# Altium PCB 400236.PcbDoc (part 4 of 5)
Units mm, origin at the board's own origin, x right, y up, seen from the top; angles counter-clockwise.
Board outline 136.53 x 63.5 mm, 4 copper layers (Top Layer, Mid-Layer 1, Mid-Layer 2, Bottom Layer), stack 1.49 mm thick; 344 components, 236 nets, 1364 pads, 1393 vias.
Unrouted connection lines stored in the file: 6.
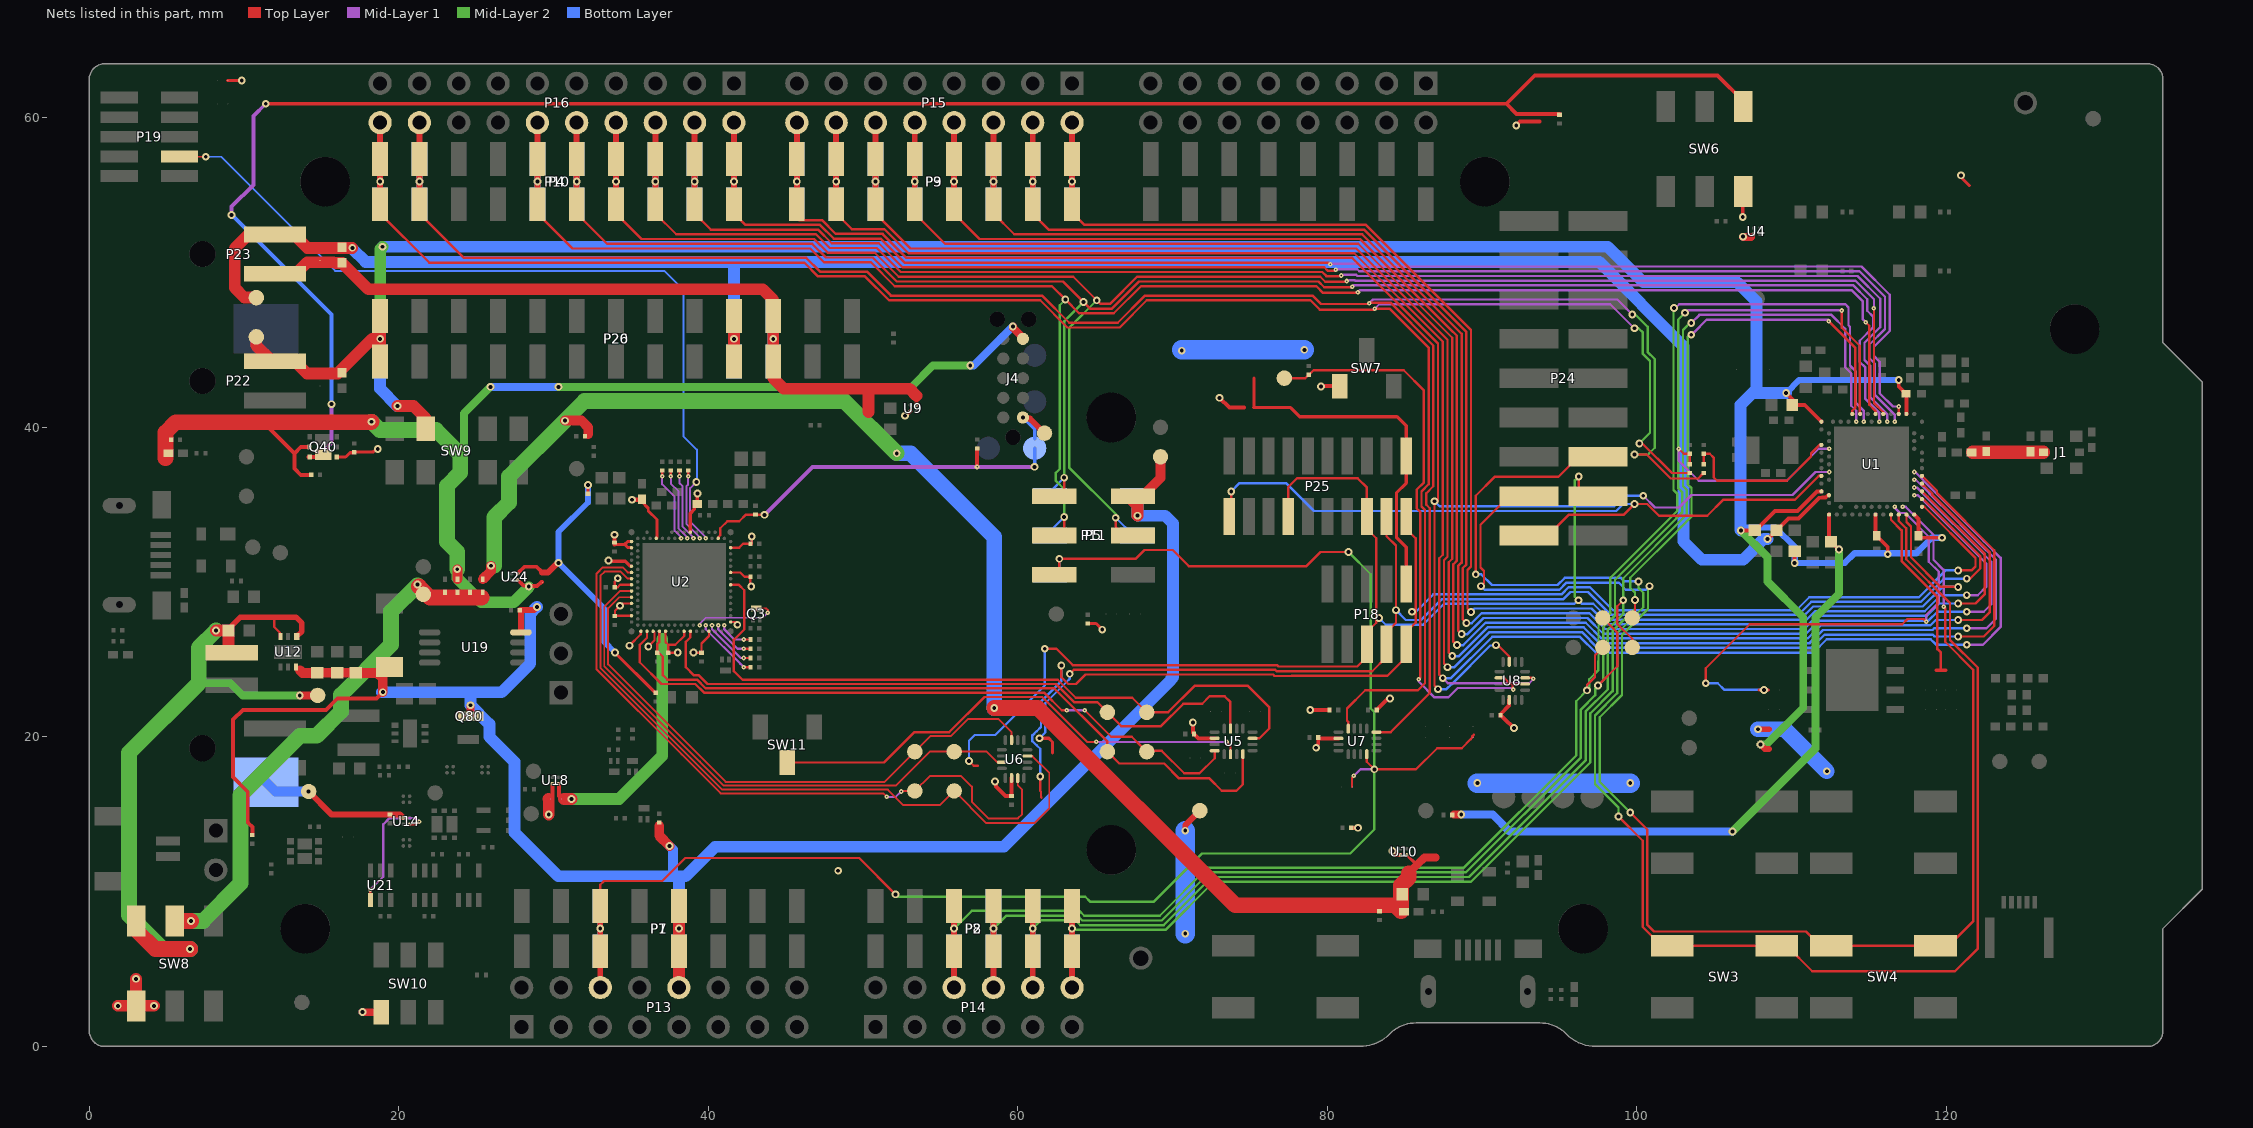
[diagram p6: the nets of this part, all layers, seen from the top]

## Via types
v1: diameter 0.5, hole 0.25, Top Layer to Bottom Layer, tented both sides, 1166 vias
v2: diameter 0.3, hole 0.1, Top Layer to Mid-Layer 1, tented top, 227 vias

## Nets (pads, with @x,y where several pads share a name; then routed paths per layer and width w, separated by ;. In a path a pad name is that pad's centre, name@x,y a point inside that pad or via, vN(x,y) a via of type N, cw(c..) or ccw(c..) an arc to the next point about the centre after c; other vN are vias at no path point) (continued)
P0.22: SB15.1 SB25.1 U1.AD18 | length 12
  Top Layer w0.152: U1.AD18@116.414,34.367 116.414,34.03 117.096,33.347 117.096,31.359 119.411,29.045 119.411,25.674 119.634,25.451 119.634,24.308
  Top Layer w0.203: SB15.1@119.337,24.308 119.634,24.308 119.957,24.308
P0.23: SB10.1 SB20.1 U1.AC19 | length 30.3
  Top Layer w0.152: v1(104.445,23.47) 104.445,24.434 107.29,27.28 117.14,27.28 117.478,27.617 118.509,27.617 v2(118.694,27.432)
  Top Layer w0.203: 107.881,23.038 v1(108.204,23.038) SB10.1@108.501,23.038
  Mid-Layer 1 w0.152: v2(116.664,34.867) 116.664,34.8 116.998,34.465 117.329,34.465 118.855,32.939 118.855,31.325 119.509,30.671 119.509,28.688 118.694,27.872 v2(118.694,27.432)
  Bottom Layer w0.152: v1(104.445,23.47) 105.225,23.47 105.656,23.038 v1(108.204,23.038)
P0.24: P24.14 SW3.2 U1.AD20 | length 103.7
  Top Layer w0.152: v1(89.586,30.505) 89.586,35.585 90.805,36.805 94.92,36.805 96.215,38.1 P24.14@97.472,38.1 ; v1(98.806,14.859) 100.37,13.295 100.37,7.72 101.588,6.502 SW3.2@102.278,6.502 SW3.2@109.028,6.502 109.691,6.502 111.328,4.864 120.548,4.864 122.025,6.341 122.025,24.468 120.221,26.272 120.221,28.663 117.401,31.482 117.401,33.473 116.914,33.961 U1.AD20@116.914,34.367
  Mid-Layer 2 w0.152: v1(98.806,14.859) 98.806,15.447 97.29,16.963 97.29,21.394 98.73,22.834 98.73,26.71 98.977,26.957 98.98,26.957 100.404,28.38 100.404,29.319 100.101,29.621 v1(100.101,30.048)
  Bottom Layer w0.152: v1(89.586,30.505) 89.941,30.505 90.627,29.82 94.871,29.82 95.328,30.277 98.948,30.277 99.177,30.048 v1(100.101,30.048)
P0.25: P24.15 SW4.2 U1.AC21 | length 95.1
  Top Layer w0.152: v1(89.916,29.743) 90.119,29.947 90.119,30.726 89.891,30.955 89.891,33.706 91.745,35.56 P24.15@93.027,35.56 ; v1(99.568,15.113) 100.675,14.006 100.675,7.846 101.09,7.43 110.921,7.43 111.85,6.502 SW4.2@112.54,6.502 SW4.2@119.29,6.502 120.137,6.502 121.72,8.085 121.72,24.345 119.918,26.147 119.918,28.316 v2(119.812,28.423) ; v2@119.812,28.448 v2@119.825,28.435
  Mid-Layer 1 w0.152: v2(117.164,34.867) 117.355,34.867 119.158,33.065 119.158,31.45 119.812,30.796 v2(119.812,28.423)
  Mid-Layer 2 w0.152: v1(99.568,15.113) 97.595,17.086 97.595,21.268 99.035,22.708 99.035,26.584 100.711,28.26 100.711,29.642 v1(100.813,29.743)
  Bottom Layer w0.152: v1(89.916,29.743) 90.145,29.515 94.997,29.515 95.455,29.972 98.822,29.972 99.279,29.515 100.584,29.515 v1(100.813,29.743)
P0.26: C51.2 R1.2 U1.G1 | length 10.8
  Top Layer w0.15: 109.55,36.551 109.674,36.551 109.675,36.552 111.244,38.12 111.244,38.214
  Top Layer w0.152: R1.2@104.318,37.66 C51.2@104.318,38.298 104.704,38.298 104.953,38.049 104.953,36.779 105.181,36.551 109.55,36.551 ; 111.244,38.214 111.244,38.32 111.791,38.867 U1.G1@111.914,38.867
P0.27: C52.2 R2.2 U1.H2 | length 13.3
  Top Layer w0.152: v2(102.692,38.608) 102.7,38.616 103.019,38.298 C52.2@103.403,38.298 R2.2@103.403,37.66
  Mid-Layer 1 w0.152: v2(102.692,38.608) 102.692,37.846 103.988,36.551 109.674,36.551 111.741,38.617 v2@112.378,38.617
  other v2: 112.414,38.617
P0.28/AIN4: P2.3 P8.3 P14.6 TP44.1 U1.B11 | length 107.4
  Top Layer w0.152: v1(96.774,23.012) 96.774,23.354 97.285,23.865 97.285,25.276 TP44.1@97.79,25.781
  Top Layer w0.381: P14.6@55.88,3.81 P2.3@55.88,6.155 v1(55.88,7.62) P2.3@55.88,9.085
  Mid-Layer 1 w0.152: v1@102.438,47.658 102.733,47.953 113.466,47.953 113.665,47.754 113.665,46.598 113.767,46.496 113.767,43.993 114.151,43.608 114.151,41.579 114.664,41.067 v2(114.664,40.367)
  Mid-Layer 2 w0.152: v1(55.88,7.62) 57.023,8.763 63.973,8.763 64.289,8.448 69.164,8.448 72.273,11.557 88.824,11.557 96.071,18.804 96.071,22.31 v1(96.774,23.012) 96.915,23.153 96.915,23.728 97.506,24.319 97.506,24.887 97.511,24.892 97.511,27.215 98.273,27.977 98.273,30.279 102.614,34.62 102.614,35.704 102.36,35.958 102.36,42.339 102.362,42.342 102.362,47.683 v1(102.387,47.709)
  Bottom Layer w0.381: P8.3@55.88,6.155 v1(55.88,7.62) P8.3@55.88,9.085
P0.29/AIN5: P2.4 P8.4 P14.8 TP45.1 U1.A10 | length 106
  Top Layer w0.152: v1(97.485,23.317) 98.73,24.562 98.73,26.746 TP45.1@97.79,27.686 ; v2(113.233,47.549) 113.233,46.445 114.397,45.281 114.397,40.884 U1.A10@114.414,40.867 ; v2@113.309,47.549 v2@113.309,47.574
  Top Layer w0.381: P14.8@58.42,3.81 P2.4@58.42,6.155 v1(58.42,7.62) P2.4@58.42,9.085
  Mid-Layer 1 w0.152: v1(103.099,47.404) 103.269,47.574 v2@113.233,47.574
  Mid-Layer 2 w0.152: v1(58.42,7.62) 59.258,8.458 63.847,8.458 64.162,8.143 69.29,8.143 72.399,11.252 88.95,11.252 96.376,18.678 96.376,21.773 97.305,22.702 97.305,23.137 v1(97.485,23.317) 97.815,23.647 97.815,27.089 98.577,27.851 98.577,30.153 102.54,34.115 102.54,34.119 102.916,34.495 102.916,35.829 102.667,36.078 102.667,46.972 v1(103.099,47.404)
  Bottom Layer w0.381: P8.4@58.42,6.155 v1(58.42,7.62) P8.4@58.42,9.652
P0.30/AIN6: P2.5 P8.5 P14.10 TP46.1 U1.B9 | length 101.3
  Top Layer w0.152: v1(99.111,28.829) 98.73,28.448 98.73,27.305 99.695,26.34 TP46.1@99.695,25.781
  Top Layer w0.381: P14.10@60.96,3.81 P2.5@60.96,6.155 v1(60.96,7.62) P2.5@60.96,9.085
  Mid-Layer 1 w0.152: v1(103.505,46.744) 104.033,47.272 112.56,47.272 113.462,46.37 113.462,43.867 113.846,43.482 113.846,41.399 114.164,41.081 v2(114.164,40.367)
  Mid-Layer 2 w0.152: v1(60.96,7.62) 61.493,8.153 63.721,8.153 64.036,7.838 69.417,7.838 72.526,10.947 89.154,10.947 96.681,18.474 96.681,21.647 98.12,23.086 98.12,26.962 99.111,27.953 v1(99.111,28.829) 99.111,30.255 103.218,34.363 103.218,35.954 102.972,36.201 102.972,46.301 103.541,46.871 v1@103.657,46.871
  Bottom Layer w0.381: P8.5@60.96,6.155 v1(60.96,7.62) P8.5@60.96,9.652
P0.31/AIN7: P2.6 P8.6 P14.12 TP47.1 U1.A8 | length 94.5
  Top Layer w0.152: TP47.1@99.695,27.686 99.873,27.864 v1(99.873,28.854) ; v2@112.446,46.863 112.446,46.801 114.092,45.155 114.092,41.256 113.914,41.077 U1.A8@113.914,40.867
  Top Layer w0.381: P14.12@63.5,3.81 P2.6@63.5,6.155 v1(63.5,7.62) P2.6@63.5,9.085
  Mid-Layer 1 w0.152: v1@103.53,46.109 103.657,46.109 104.513,46.965 112.344,46.965 v2@112.446,46.863
  Mid-Layer 2 w0.152: v1(63.5,7.62) 63.587,7.533 69.543,7.533 72.652,10.643 89.28,10.643 96.986,18.348 96.986,21.521 98.425,22.96 98.425,26.836 99.873,28.284 v1(99.873,28.854) 99.873,29.335 99.57,29.637 99.57,30.284 102.868,33.581 102.868,33.584 103.521,34.237 103.521,36.08 103.274,36.326 103.274,40.968 103.276,40.97 103.276,45.855 v1@103.53,46.109 ; v1@103.594,46.045 v1@103.657,46.109
  Bottom Layer w0.381: P8.6@63.5,6.155 v1(63.5,7.62) P8.6@63.5,9.085
  other v1: 103.505,45.982
  other v2: 112.395,46.863
P1.00: P18.6 P24.16 P25.6 P25.14 SB57.1 U1.AD22 | length 107.9
  Top Layer w0.152: v1(56.845,18.44) 57.15,18.136 57.222,18.136 SB57.1@57.396,18.136 ; v1(61.733,25.694) 62.498,25.694 63.552,24.64 76.75,24.64 76.837,24.554 81.932,24.554 82.55,25.171 P18.6@82.55,25.99 82.55,26.773 83.159,27.381 83.159,32.843 82.55,33.452 P25.6@82.55,34.245 82.55,36.119 81.952,36.716 78.042,36.716 77.47,36.144 P25.14@77.47,34.245 ; v1(96.241,36.83) 96.241,36.119 96.799,35.56 P24.16@97.472,35.56 ; U1.AD22@117.414,34.367 117.414,33.892 117.704,33.602 117.704,31.607 119.618,29.693 v1(120.752,29.693)
  Mid-Layer 2 w0.152: v1(96.215,28.829) 95.987,29.058 95.987,36.576 v1(96.241,36.83)
  Bottom Layer w0.152: v1(56.845,18.44) 56.845,19.753 57.217,20.125 58.541,20.125 61.738,23.322 61.738,25.689 v1(61.733,25.694) ; v1(83.337,27.686) 83.768,27.254 86.182,27.254 87.528,28.6 95.961,28.6 96.19,28.829 v1(96.215,28.829) 96.444,28.6 97.179,28.6 98.2,27.58 106.02,27.58 106.022,27.582 110.54,27.582 111.383,28.425 118.464,28.425 119.731,29.693 v1(120.752,29.693)
P1.01: P3.1 P9.1 P15.2 U1.Y23 | length 99.5
  Top Layer w0.152: P3.1@63.5,54.415 63.5,53.899 64.313,53.086 82.493,53.086 89.281,46.298 89.281,31.013 89.052,30.785 89.052,28.296 v1(89.281,28.067)
  Top Layer w0.381: P3.1@63.5,54.415 v1(63.5,55.88) P3.1@63.5,57.345 P15.2@63.5,59.69
  Mid-Layer 1 w0.152: v2(117.914,35.617) 118.154,35.617 122.58,31.191 122.58,29.718 122.022,29.159 v1(121.31,29.159)
  Bottom Layer w0.152: v1(89.281,28.067) 89.51,28.296 97.056,28.296 98.074,27.277 107.694,27.277 107.696,27.28 110.665,27.28 111.509,28.123 118.589,28.123 119.625,29.159 v1(121.31,29.159)
  Bottom Layer w0.381: P9.1@63.5,53.807 v1(63.5,55.88) P9.1@63.5,57.345
P1.02: P3.2 P9.2 P15.4 U1.W24 | length 102.5
  Top Layer w0.152: P3.2@60.96,54.415 60.96,53.797 61.976,52.781 82.367,52.781 88.976,46.172 88.976,31.14 88.748,30.911 88.748,27.584 v1(88.976,27.356) ; U1.W24@118.414,35.867 118.431,35.867 118.78,35.519 118.78,35.515 122.479,31.816 122.479,29.235 121.869,28.626 v1(120.752,28.626)
  Top Layer w0.381: P3.2@60.96,54.415 v1(60.96,55.88) P3.2@60.96,57.345 P15.4@60.96,59.69
  Bottom Layer w0.152: v1(88.976,27.356) 89.324,27.356 89.959,27.991 96.933,27.991 97.949,26.975 110.788,26.975 111.634,27.821 118.714,27.821 119.519,28.626 v1(120.752,28.626)
  Bottom Layer w0.381: P9.2@60.96,54.415 v1(60.96,55.88) P9.2@60.96,57.345
P1.03: P3.3 P9.3 P15.6 U1.V23 | length 107.4
  Top Layer w0.152: P3.3@58.42,54.415 58.42,53.823 59.766,52.476 82.241,52.476 88.671,46.046 88.671,31.266 88.443,31.037 88.443,26.873 v1(88.671,26.645)
  Top Layer w0.381: P3.3@58.42,54.415 v1(58.42,55.88) P3.3@58.42,57.345 P15.6@58.42,59.69
  Mid-Layer 1 w0.152: v2(117.914,36.117) 118.085,36.117 122.885,31.317 122.885,28.575 122.403,28.092 v1(121.31,28.092)
  Bottom Layer w0.152: v1(88.671,26.645) 89.052,26.645 90.094,27.686 96.81,27.686 97.826,26.67 110.911,26.67 111.759,27.518 118.839,27.518 119.414,28.092 v1(121.31,28.092)
  Bottom Layer w0.381: P9.3@58.42,54.415 v1(58.42,55.88) P9.3@58.42,57.345
P1.04: P3.4 P9.4 P15.8 U1.U24 | length 111
  Top Layer w0.152: P3.4@55.88,54.415 55.88,53.823 57.531,52.172 82.114,52.172 87.956,46.33 88.367,45.919 88.367,31.392 88.138,31.164 88.138,26.162 v1(88.367,25.933) ; U1.U24@118.414,36.367 118.414,36.307 118.487,36.233 118.565,36.233 119.084,35.714 119.084,35.641 122.783,31.942 122.783,28.041 122.301,27.559 v1(120.752,27.559)
  Top Layer w0.381: P3.4@55.88,54.415 v1(55.88,55.88) P3.4@55.88,57.345 P15.8@55.88,59.69
  Bottom Layer w0.152: v1(88.367,25.933) 88.773,25.933 90.221,27.381 96.687,27.381 97.703,26.365 111.034,26.365 111.885,27.216 118.965,27.216 119.308,27.559 v1(120.752,27.559)
  Bottom Layer w0.381: P9.4@55.88,54.415 v1(55.88,55.88) P9.4@55.88,57.345
P1.05: P3.5 P9.5 P15.10 U1.T23 | length 115.8
  Top Layer w0.152: P3.5@53.34,54.415 53.34,53.823 55.296,51.867 81.988,51.867 88.062,45.793 88.062,31.518 87.833,31.29 87.833,31.013 87.833,26.848 87.833,25.451 v1(88.062,25.222)
  Top Layer w0.381: P3.5@53.34,54.415 v1(53.34,55.88) P3.5@53.34,57.345 P15.10@53.34,59.69
  Mid-Layer 1 w0.152: v2(117.914,36.617) 118.016,36.617 119.684,34.95 119.686,34.95 122.072,32.564 122.072,32.561 123.19,31.444 123.19,27.635 122.58,27.026 v1(121.31,27.026)
  Bottom Layer w0.152: v1(88.062,25.222) 88.493,25.222 90.347,27.076 96.564,27.076 97.58,26.06 111.157,26.06 112.01,26.913 119.09,26.913 119.202,27.026 v1(121.31,27.026)
  Bottom Layer w0.381: P9.5@53.34,54.415 v1(53.34,55.88) P9.5@53.34,57.345
P1.06: P3.6 P9.6 P15.12 U1.R24 | length 119.5
  Top Layer w0.152: P3.6@50.8,54.415 50.8,53.823 53.061,51.562 81.862,51.562 87.757,45.667 87.757,31.645 87.528,31.416 87.528,31.14 87.528,31.115 87.528,26.822 87.528,24.74 v1(87.757,24.511) ; U1.R24@118.414,36.867 118.431,36.867 119.389,35.909 119.389,35.767 123.088,32.068 123.088,27.178 122.403,26.492 v1(120.752,26.492)
  Top Layer w0.381: P3.6@50.8,54.415 v1(50.8,55.88) P3.6@50.8,57.345 P15.12@50.8,59.69
  Bottom Layer w0.152: v1(87.757,24.511) 88.213,24.511 90.473,26.772 96.442,26.772 97.458,25.756 111.28,25.756 112.135,26.611 119.107,26.611 119.225,26.492 v1(120.752,26.492)
  Bottom Layer w0.381: P9.6@50.8,54.415 v1(50.8,55.88) P9.6@50.8,57.345
P1.07: P3.7 P9.7 P15.14 U1.P23 U8.3 | length 130.9
  Top Layer w0.152: P3.7@48.26,54.415 48.26,53.823 49.276,52.807 51.385,52.807 52.934,51.257 81.736,51.257 87.452,45.541 87.452,31.771 87.224,31.542 87.224,31.266 87.224,30.989 87.224,24.028 v1(87.452,23.8) ; U8.3@92.773,23.822 93.196,23.822 v2@93.294,23.724
  Top Layer w0.381: P3.7@48.26,54.415 v1(48.26,55.88) P3.7@48.26,57.345 P15.14@48.26,59.69
  Mid-Layer 1 w0.152: v1(87.452,23.8) 87.782,23.47 93.04,23.47 v2@93.294,23.724 ; v2(117.914,37.117) 117.984,37.117 118.515,36.587 118.515,36.552 122.415,32.652 ; v1(121.31,25.959) 122.352,25.959 123.495,27.102 123.495,31.57 122.415,32.649
  Bottom Layer w0.152: v1(87.452,23.8) 87.986,23.8 90.653,26.467 96.319,26.467 97.337,25.448 106.398,25.448 106.401,25.451 111.406,25.451 112.264,26.309 118.975,26.309 119.223,26.06 119.227,26.06 119.328,25.959 v1(121.31,25.959)
  Bottom Layer w0.381: P9.7@48.26,54.415 v1(48.26,55.88) P9.7@48.26,57.345
  other v2: 93.294,23.749
P1.08: P3.8 P9.8 P15.16 U1.P2 U8.7 | length 109.9
  Top Layer w0.152: P3.8@45.72,54.415 45.72,53.543 45.872,53.391 47.339,53.391 48.228,52.502 51.259,52.502 52.808,50.952 81.609,50.952 87.147,45.414 v1@87.147,35.23 ; v1(86.919,35.23) 86.919,31.392 86.919,30.863 86.919,23.317 v1(87.147,23.089) ; v1(90.884,25.93) 91.013,25.93 91.748,25.196 U8.7@91.748,24.847
  Top Layer w0.381: P3.8@45.72,54.415 v1(45.72,55.88) P3.8@45.72,57.345 P15.16@45.72,59.69
  Mid-Layer 1 w0.152: v1(100.406,35.585) 101.171,34.821 102.715,34.821 103.53,35.636 110.053,35.636 111.534,37.117 v2(112.414,37.117)
  Bottom Layer w0.152: v1(86.919,35.23) 87.249,34.9 98.531,34.9 99.217,35.585 v1(100.406,35.585) ; v1(87.147,23.089) 87.69,23.089 87.995,23.393 88.01,23.393 90.522,25.905 v1@90.884,25.905
  Bottom Layer w0.381: P9.8@45.72,54.415 v1(45.72,55.88) P9.8@45.72,57.345
P1.09: P24.17 P25.20 U1.R1 | length 51
  Top Layer w0.15: 110.058,35.331 110.203,35.331 111.739,36.867 U1.R1@111.914,36.867
  Top Layer w0.152: P25.20@73.66,33.401 P25.20@73.66,34.245 73.787,34.372 v1(73.787,35.865) ; P24.17@93.027,33.02 94.259,33.02 95.606,34.366 99.162,34.366 v1(99.847,35.052) 100.66,35.052 101.422,34.29 104.546,34.29 105.588,35.331 110.058,35.331
  Bottom Layer w0.152: v1@73.66,35.738 v1(73.787,35.865) 74.32,36.398 77.326,36.398 79.129,34.595 98.658,34.595 99.115,35.052 v1(99.847,35.052)
P1.10: P4.1 P10.1 P16.2 U1.A20 | length 94.7
  Top Layer w0.152: P4.1@41.656,54.415 41.656,53.823 42.393,53.086 47.213,53.086 48.102,52.197 51.132,52.197 52.682,50.648 80.061,50.648 v2(80.173,50.535) ; U1.A20@116.914,40.867 v2(116.914,41.351)
  Top Layer w0.381: P4.1@41.656,54.415 v1(41.656,55.88) P4.1@41.656,57.345 P16.2@41.656,59.69
  Mid-Layer 1 w0.152: v2(80.173,50.535) 80.217,50.579 81.994,50.579 82.179,50.394 114.499,50.394 116.327,48.565 116.327,46.229 115.311,45.213 115.311,44.603 115.675,44.24 115.675,42.211 116.534,41.351 v2(116.914,41.351)
  Bottom Layer w0.381: P10.1@41.656,54.415 v1(41.656,55.88) P10.1@41.656,57.345
P1.11: P4.2 P10.2 P16.4 U1.B19 | length 97.2
  Top Layer w0.152: P4.2@39.116,54.415 39.116,53.823 40.157,52.781 47.086,52.781 47.975,51.892 51.006,51.892 52.556,50.343 79.795,50.343 80.006,50.131 80.49,50.131 v2(80.533,50.175)
  Top Layer w0.381: P4.2@39.116,54.415 v1(39.116,55.88) P4.2@39.116,57.345 P16.4@39.116,59.69
  Mid-Layer 1 w0.152: v2(80.533,50.175) 80.577,50.219 81.922,50.219 82.052,50.089 114.372,50.089 116.023,48.439 116.023,46.356 115.007,45.34 115.007,44.477 115.37,44.113 115.37,42.084 116.664,40.791 v2(116.664,40.367)
  Bottom Layer w0.381: P10.2@39.116,54.415 v1(39.116,55.88) P10.2@39.116,57.345
P1.12: P4.3 P10.3 P16.6 U1.B17 | length 99.3
  Top Layer w0.152: P4.3@36.576,54.415 36.576,53.823 37.922,52.476 46.96,52.476 47.849,51.587 50.88,51.587 52.429,50.038 79.669,50.038 79.935,49.771 80.85,49.771 v2(80.893,49.815)
  Top Layer w0.381: P4.3@36.576,54.415 v1(36.576,55.88) P4.3@36.576,57.345 P16.6@36.576,59.69
  Mid-Layer 1 w0.152: v2(80.893,49.815) 80.937,49.859 81.851,49.859 81.926,49.784 114.246,49.784 115.718,48.312 115.718,46.482 114.702,45.466 114.702,44.351 115.065,43.987 115.065,41.958 116.164,40.86 v2(116.164,40.367)
  Bottom Layer w0.381: P10.3@36.576,54.415 v1(36.576,55.88) P10.3@36.576,57.345
P1.13: P4.4 P5.4 P10.4 P11.4 P16.8 U1.A16 | length 121.1
  Top Layer w0.152: P4.4@34.036,54.415 34.036,53.823 35.687,52.172 46.834,52.172 47.723,51.283 50.754,51.283 52.303,49.733 63.576,49.733 v1(65.1,48.209) 65.329,47.981 65.947,47.981 67.7,49.733 79.542,49.733 79.864,49.412 81.209,49.412 v2(81.253,49.455) ; v1(66.319,34.163) 66.319,33.579 66.878,33.02 P5.4@67.119,33.02 ; v2(115.291,47.701) 115.311,47.68 115.311,41.584 115.914,40.982 U1.A16@115.914,40.867
  Top Layer w0.381: P4.4@34.036,54.415 v1(34.036,55.88) P4.4@34.036,57.345 P16.8@34.036,59.69
  Mid-Layer 1 w0.152: v2(81.253,49.455) 81.297,49.499 81.78,49.499 81.8,49.479 114.12,49.479 115.316,48.283 115.316,47.727 v2(115.291,47.701)
  Mid-Layer 2 w0.152: v1(65.1,48.209) 65.093,48.209 63.312,46.429 63.312,37.402 66.319,34.394 v1(66.319,34.163)
  Bottom Layer w0.152: v1(66.319,34.163) 67.462,33.02 P11.4@67.722,33.02
  Bottom Layer w0.381: P10.4@34.036,54.415 v1(34.036,55.88) P10.4@34.036,57.345
P1.14: P4.5 P5.1 P10.5 P11.1 P16.10 U1.B15 | length 120.3
  Top Layer w0.152: P4.5@31.496,54.415 31.496,53.823 33.452,51.867 46.708,51.867 47.597,50.978 50.627,50.978 52.177,49.428 62.916,49.428 v1(64.237,48.108) 64.668,47.676 66.074,47.676 67.826,49.428 79.416,49.428 79.793,49.052 81.569,49.052 v2(81.613,49.095) ; P5.1@62.674,35.56 62.992,35.878 v1(62.992,36.754)
  Top Layer w0.381: P4.5@31.496,54.415 v1(31.496,55.88) P4.5@31.496,57.345 P16.10@31.496,59.69
  Mid-Layer 1 w0.152: v2(81.613,49.095) 81.692,49.174 113.994,49.174 114.884,48.284 114.884,47.537 115.252,47.169 115.252,46.447 114.397,45.592 114.397,44.225 114.761,43.861 114.761,41.832 115.664,40.929 v2(115.664,40.367)
  Mid-Layer 2 w0.152: v1(62.992,36.754) 63.007,36.769 63.007,46.878 v1(64.237,48.108)
  Bottom Layer w0.152: P11.1@61.473,35.56 P11.1@62.072,35.56 62.072,35.834 v1(62.992,36.754)
  Bottom Layer w0.381: P10.5@31.496,54.415 v1(31.496,55.88) P10.5@31.496,57.345
P1.15: P4.6 P5.3 P10.6 P11.3 P16.12 U1.A14 | length 123.4
  Top Layer w0.152: P4.6@28.956,54.415 28.956,53.823 31.217,51.562 46.581,51.562 47.47,50.673 50.501,50.673 52.051,49.124 62.205,49.124 v1(63.068,48.26) 63.957,47.371 66.2,47.371 67.952,49.124 79.29,49.124 79.722,48.692 81.929,48.692 v2(81.973,48.735) ; P5.3@62.674,33.02 62.992,33.338 v1(62.992,34.214) ; v2(114.783,46.787) 115.007,46.563 115.007,41.457 115.414,41.05 U1.A14@115.414,40.867
  Top Layer w0.381: P4.6@28.956,54.415 v1(28.956,55.88) P4.6@28.956,57.345 P16.12@28.956,59.69
  Mid-Layer 1 w0.152: v2(81.973,48.735) 82.107,48.87 113.867,48.87 114.579,48.158 114.579,47.012 v2@114.783,46.809
  Mid-Layer 2 w0.152: v1(62.992,34.214) 62.992,35.999 62.459,36.533 62.459,37.069 62.702,37.313 62.702,47.894 v1(63.068,48.26)
  Bottom Layer w0.152: P11.3@62.072,33.02 62.072,33.294 v1(62.992,34.214)
  Bottom Layer w0.381: P10.6@28.956,54.415 v1(28.956,55.88) P10.6@28.956,57.345
RESET_PIN: P1.3 P5.5 P7.3 P11.5 P13.6 SB43.2 SB44.1 U7.4 | length 114.6
  Top Layer w0.152: P1.3@33.02,9.085 33.02,10.445 33.268,10.693 37.023,10.693 38.506,12.177 49.748,12.177 v1(52.095,9.83) ; P5.5@62.679,30.485 v1(62.679,31.506) 67.6,31.506 68.174,32.08 70.002,32.08 71.044,31.039 78.638,31.039 79.553,31.953 v1(81.356,31.953) ; 81.592,16.764 81.592,17.117 81.592,17.356 v2@81.737,17.501 ; U7.4@82.54,18.885 82.54,18.399 v1(83.033,17.907) 85.724,17.907 87.091,19.275 88.675,19.275 89.259,19.859 89.408,20.008 ; 89.366,20.049 89.459,20.142
  Top Layer w0.381: P13.6@33.02,3.81 P1.3@33.02,6.155 v1(33.02,7.62) P1.3@33.02,9.085
  Mid-Layer 1 w0.152: v2@81.737,17.501 82.144,17.907 v1(83.033,17.907)
  Mid-Layer 2 w0.152: v1(52.095,9.83) 52.248,9.677 64.352,9.677 64.667,9.362 68.785,9.362 71.894,12.471 81.471,12.471 83.027,14.027 83.027,15.23 83.033,15.236 v1(83.033,17.907) 83.033,21.608 82.803,21.837 82.803,30.506 v1(81.356,31.953)
  Bottom Layer w0.152: P11.5@62.679,30.48 v1(62.679,31.506)
  Bottom Layer w0.381: P7.3@33.02,6.155 v1(33.02,7.62) P7.3@33.02,9.085
  other v2: 81.712,17.501
RF: C4.2 C22.1 J1.1 L1.2 | length 4.6
  Top Layer w0.871: L1.2@121.681,38.379 J1.1@126.25,38.379
SCL: P4.10 P10.10 P16.20 R2.1 U7.12 | length 140.5
  Top Layer w0.152: P4.10@18.796,54.415 18.796,53.823 21.971,50.648 46.203,50.648 47.092,49.759 50.122,49.759 51.672,48.209 61.442,48.209 63.194,46.457 66.579,46.457 68.331,48.209 78.911,48.209 79.508,47.612 83.009,47.612 v2(83.053,47.656) 84.044,47.656 86.538,45.162 86.538,36.321 86.081,35.864 86.081,34.883 86.309,34.654 86.309,23.47 85.852,23.012 82.448,23.012 81.267,21.831 81.267,21.044 81.34,20.971 U7.12@81.34,20.535 ; v1(100.152,38.964) 100.347,38.964 102.258,37.053 R2.1@103.403,37.053
  Top Layer w0.381: P4.10@18.796,54.415 v1(18.796,55.88) P4.10@18.796,57.345 P16.20@18.796,59.69
  Mid-Layer 1 w0.152: v2(83.053,47.656) 83.352,47.955 98.273,47.955 99.822,46.406 v1(99.847,46.406)
  Mid-Layer 2 w0.152: v1(99.847,46.406) 100.101,46.406 100.381,46.126 100.381,44.751 100.838,44.294 100.838,39.649 v1(100.152,38.964)
  Bottom Layer w0.381: P10.10@18.796,54.415 v1(18.796,55.88) P10.10@18.796,57.345
SDA: P4.9 P10.9 P16.18 R1.1 U7.8 | length 140.2
  Top Layer w0.152: P4.9@21.336,54.415 21.336,53.823 24.206,50.952 46.329,50.952 47.218,50.063 50.249,50.063 51.798,48.514 61.568,48.514 63.321,46.761 66.452,46.761 68.205,48.514 79.037,48.514 79.579,47.972 82.649,47.972 v2(82.693,48.016) 82.736,48.059 84.071,48.059 86.843,45.288 86.843,36.195 86.385,35.738 86.385,35.009 86.614,34.78 86.614,22.835 84.089,20.31 U7.8@83.165,20.31 ; v1(99.847,38.252) 100.627,38.252 102.183,36.697 103.962,36.697 104.244,36.979 104.244,36.994 104.303,37.053 R1.1@104.318,37.053
  Top Layer w0.381: P4.9@21.336,54.415 v1(21.336,55.88) P4.9@21.336,57.345 P16.18@21.336,59.69
  Mid-Layer 1 w0.152: v2(82.693,48.016) 82.937,48.26 98.73,48.26 v1(99.695,47.295)
  Mid-Layer 2 w0.152: v1(99.695,47.295) 99.892,47.295 100.686,46.501 100.686,44.878 101.143,44.42 101.143,38.684 100.711,38.252 v1(99.847,38.252)
  Bottom Layer w0.381: P10.9@21.336,54.415 v1(21.336,55.88) P10.9@21.336,57.345
SWD0_CLK: R12.1 U2.B18 | length 4.8
  Top Layer w0.152: v2(37.579,36.834) R12.1@37.579,37.209
  Mid-Layer 1 w0.125: v2(37.579,36.834) 37.579,36.361 38.076,35.864 38.076,33.464 38.376,33.164 38.379,33.164 38.576,32.967 38.576,32.964 38.639,32.902 v2(38.639,32.827)
SWD0_IO: R11.1 U2.B16 | length 4.9
  Top Layer w0.152: v2(37.021,36.834) R11.1@37.021,37.209
  Mid-Layer 1 w0.125: v2(37.021,36.834) 37.021,36.32 37.826,35.514 37.826,33.317 38.176,32.967 38.176,32.889 v2(38.239,32.827)
SWD0_RESET: R15.1 U2.B22 | length 4.8
  Top Layer w0.152: v2(38.697,36.834) R15.1@38.697,37.209
  Mid-Layer 1 w0.125: v2(38.697,36.834) 38.697,36.31 38.576,36.189 38.576,33.767 39.376,32.967 39.376,32.914 39.439,32.852 v2(39.439,32.827)
SWD0_SEL: P19.3 U2.B24 | length 53.1
  Top Layer w0.125: P19.3@5.836,57.506 5.857,57.484 v1(7.529,57.484)
  Mid-Layer 1 w0.125: v1(39.225,36.475) 38.826,36.076 38.826,33.917 39.776,32.967 39.776,32.889 v2(39.839,32.827)
  Bottom Layer w0.125: v1(7.529,57.484) 8.519,57.484 15.885,50.118 37.164,50.118 38.383,48.899 38.383,39.44 39.256,38.567 39.256,36.506 v1(39.225,36.475)
SWD0_SWO: R14.1 U2.B20 | length 4.8
  Top Layer w0.152: v2(38.138,36.834) R14.1@38.138,37.209
  Mid-Layer 1 w0.125: v2(38.138,36.834) 38.138,36.402 38.326,36.214 38.326,33.617 38.976,32.967 38.976,32.914 39.039,32.852 v2(39.039,32.827)
SWD1_CLK: R17.1 U2.AK28 | length 2.9
  Top Layer w0.152: v2(42.3,25.7) R17.1@42.715,25.7
  Mid-Layer 1 w0.152: v2(40.639,27.227) 40.639,26.946 41.885,25.7 v2(42.3,25.7)
SWD1_IO: R16.1 U2.AK30 | length 2.2
  Top Layer w0.152: v2(42.3,26.3) R16.1@42.715,26.3
  Mid-Layer 1 w0.152: v2(41.039,27.227) 41.039,26.938 41.677,26.3 v2(42.3,26.3)
SWD1_RESET: R19.1 U2.AK24 | length 4.2
  Top Layer w0.152: v2(42.3,24.5) R19.1@42.715,24.5
  Mid-Layer 1 w0.152: v2(39.839,27.227) 39.839,26.961 42.063,24.737 v2(42.3,24.5)
SWD1_SEL: Q3.3 U2.AK22 | length 5.8
  Top Layer w0.125: Q3.3@43.1,28.3 43.75,28.3 43.85,28.2 v2(43.85,28.025)
  Mid-Layer 1 w0.125: v2(39.439,27.227) 39.439,27.274 39.501,27.337 39.501,27.367 39.835,27.7 43.525,27.7 v2(43.85,28.025)
SWD1_SWO: R18.1 U2.AK26 | length 3.5
  Top Layer w0.152: v2(42.3,25.1) R18.1@42.715,25.1
  Mid-Layer 1 w0.152: v2(40.239,27.227) 40.239,26.954 42.092,25.1 v2(42.3,25.1)
SWD3_CLK: TP6.1 U2.R1 U6.3 | length 46.7
  Top Layer w0.125: U2.R1@35.039,30.227 35.02,30.246 34.773,30.246 34.331,30.688 33.294,30.688 33.025,30.419 33.025,24.479 40.904,16.6 51.6,16.6 52.604,15.596 54.966,15.596 TP6.1@55.88,16.51 57.963,14.427 61.062,14.427 62.027,15.392 62.027,17.678 60.938,18.767 U6.3@60.617,18.767
SWD3_IO: TP5.1 U2.N1 U6.15 | length 44.5
  Top Layer w0.125: U2.N1@35.039,30.627 34.789,30.627 34.466,30.95 33.175,30.95 32.775,30.55 32.775,24.375 38.275,18.875 40.8,16.35 51.3,16.35 v2(51.525,16.125) ; v2(52.475,16.475) 52.51,16.51 TP5.1@53.34,16.51 54.305,17.475 56.337,17.475 57.023,16.789 57.023,15.798 58.089,14.732 59.995,14.732 60.274,15.011 60.274,16.588 59.992,16.87 U6.15@59.992,17.342
  Mid-Layer 1 w0.125: v2(51.525,16.125) 52.125,16.125 v2(52.475,16.475)
SWD3_RESET: TP7.1 U2.AA1 U6.7 | length 37.2
  Top Layer w0.125: U2.AA1@35.039,29.027 34.23,29.027 33.525,28.321 33.525,24.686 41.111,17.1 51.39,17.1 54.34,20.05 55.675,20.05 56.775,21.15 58.758,21.15 59.592,20.317 U6.7@59.592,19.792
SWD3_SWO: TP8.1 U2.W1 U6.11 | length 36.1
  Top Layer w0.125: U2.W1@35.039,29.427 34.792,29.427 34.277,29.427 33.275,28.425 33.275,24.582 39.45,18.407 41.007,16.85 52.112,16.85 54.312,19.05 57.983,19.05 58.665,18.367 U6.11@58.967,18.367
SWDCLK: P18.4 P25.4 SB55.1 U1.AA24 | length 83.9
  Top Layer w0.152: v1@61.374,19.736 61.392,19.754 v1(61.392,19.914) ; v1(63.349,24.078) 63.607,24.335 76.624,24.335 76.71,24.249 82.897,24.249 83.82,25.171 P18.4@83.82,25.99 83.82,26.773 84.429,27.381 v1(84.429,28.194) 84.429,32.36 83.82,32.968 P25.4@83.82,34.245 ; U1.AA24@118.414,35.367 118.496,35.367 122.174,31.689 122.174,30.886 v1@121.514,30.226
  Top Layer w0.203: v1(61.392,19.914) 62.001,19.914 62.238,19.677 62.238,19.327 SB55.1@62.238,18.974
  Bottom Layer w0.152: v1(61.392,19.914) 61.775,20.297 61.775,22.182 63.289,23.696 63.296,23.696 63.349,23.749 v1(63.349,24.078) ; v1(84.429,28.194) 85.064,27.559 86.056,27.559 87.402,28.905 95.25,28.905 95.707,29.362 96.844,29.362 98.322,27.884 110.415,27.884 111.258,28.728 118.338,28.728 119.837,30.226 v1(121.31,30.226)
SWDIO: P18.2 P25.2 SB54.1 U1.AC24 | length 87.1
  Top Layer w0.152: v1(61.443,17.45) 61.443,16.505 61.493,16.454 61.493,16.111 SB54.1@61.526,16.078 ; v1(62.81,24.616) 62.81,23.862 63.254,23.419 63.754,23.419 64.366,24.03 76.498,24.03 76.589,23.939 77.682,23.939 77.687,23.944 83.863,23.944 85.09,25.171 P18.2@85.09,25.99 85.09,26.773 85.699,27.381 85.699,32.843 85.09,33.452 P25.2@85.09,34.245 ; U1.AC24@118.414,34.867 118.565,34.867 121.869,31.563 121.869,31.012 121.616,30.759 v1(120.752,30.759)
  Bottom Layer w0.152: v1(61.443,17.45) 61.443,19.232 61.213,19.462 61.205,19.462 60.941,19.727 60.941,20.1 61.205,20.365 61.215,20.365 61.498,20.648 61.498,22.297 62.81,23.61 v1(62.81,24.616) ; 85.725,28.092 86.843,29.21 95.124,29.21 95.581,29.667 96.967,29.667 98.448,28.187 110.29,28.187 111.133,29.03 118.213,29.03 119.942,30.759 v1(120.752,30.759)
  other v1: 85.471,28.092
TRACE_SW: R4.1 TP23.1 U8.2 U8.10 | length 37.7
  Top Layer w0.152: TP23.1@77.216,43.18 78.568,43.18 R4.1@78.717,43.329 ; R4.1@78.791,43.403 78.85,43.462 78.877,43.462 79.107,43.691 84.934,43.691 86.233,42.393 86.233,36.448 85.776,35.99 85.776,34.756 86.004,34.528 86.004,23.825 v2(85.903,23.724) ; U8.10@91.123,23.822 91.418,23.822 91.818,23.422 91.973,23.422 ; v2@91.973,23.114 91.973,23.422 ; U8.2@92.773,23.422 91.973,23.422
  Mid-Layer 1 w0.152: v2(85.903,23.724) 85.903,23.579 86.926,22.555 87.808,22.555 88.417,23.165 91.923,23.165 v2@91.999,23.089
  other v2: 91.999,23.063
U\A\R\T\_\F\C\_\O\F\F\: SW11.2 U5.2 | length 32.3
  Top Layer w0.152: SW11.2@45.1,18.35 51.35,18.35 53.314,20.314 55.566,20.314 57.836,22.584 61.578,22.584 64.487,19.675 65.05,19.675 v2(65.075,19.7) ; v2(73.5,19.675) 73.739,19.436 U5.2@73.739,18.885
  Mid-Layer 1 w0.152: v2(65.075,19.7) 65.1,19.675 v2(73.5,19.675)
USB_DETECT: Q40.3 R26.1 SB31.2 SW6.3 | length 128.6
  Top Layer w0.254: v1(11.405,60.909) 91.567,60.909 ; Q40.3@14.163,38.085 14.742,38.085 v2(15.113,38.456) ; R26.1@94.996,60.241 94.982,60.255 92.221,60.255 91.567,60.909 ; SW6.3@106.869,60.484 106.869,61.076 105.207,62.738 93.396,62.738 91.567,60.909
  Mid-Layer 1 w0.254: v1(9.2,53.721) 9.2,54.26 10.604,55.664 10.604,60.109 v1(11.405,60.909) ; v2(15.113,38.456) 15.646,38.989 v1(15.646,41.504)
  Bottom Layer w0.254: v1@9.22,53.721 15.646,47.294 v1(15.646,41.504)
V5V: C82.2 C83.2 C85.2 C96.2 D84.2 P1.5 P5.2 P7.5 P11.2 P13.10 Q80.2 R83.1 R93.1 TP36.1 U12.6 U19.8 | length 134.5
  Top Layer w0.254: R83.1@10.538,13.671 10.538,14.176 10.259,14.456 10.259,14.478 10.244,14.493 10.244,16.452 9.296,17.399 9.296,21.121 9.925,21.75 15.3,21.75 16.025,22.475 18.553,22.475 v1(18.97,22.892)
  Top Layer w0.381: C85.2@27.856,28.194 28.727,28.194 v1(28.931,28.397) ; U19.8@27.893,26.756 C85.2@27.893,28.157
  Top Layer w0.508: Q80.2@24.639,21.336 v1(24.639,22.046)
  Top Layer w0.635: 13.612,24.307 13.779,24.14 14.715,24.14 C82.2@14.725,24.15 C83.2@16.025,24.15 16.03,24.145 C96.2@17.21,24.145 ; C96.2@17.215,24.14 18.598,24.14 18.97,23.768 v1(18.97,22.892) ; C96.2@17.218,24.143 C96.2@17.22,24.145 ; 36.83,14.257 36.83,13.614 v1(37.49,12.954) ; P5.2@67.119,35.56 68.047,35.56 69.215,36.728 TP36.1@69.215,38.1
  Top Layer w0.762: P13.10@38.1,3.81 P1.5@38.1,6.155 v1(38.1,7.62) P1.5@38.1,9.085 ; P5.2@67.119,35.56 67.722,34.957 v1(67.722,34.296)
  Bottom Layer w0.508: 24.639,22.81 24.714,22.885
  Bottom Layer w0.635: v1(37.49,12.954) 37.719,12.725 37.719,10.998
  Bottom Layer w0.762: v1@18.923,22.885 24.714,22.885 26.645,22.885 28.499,24.74 28.499,27.965 v1(28.931,28.397) ; 24.639,22.81 v1(24.639,22.046) 25.857,20.828 25.857,20.015 27.47,18.402 27.47,13.83 30.302,10.998 37.719,10.998 38.125,10.998 ; P7.5@38.1,6.155 v1(38.1,7.62) P7.5@38.1,9.085 38.1,10.973 38.125,10.998 ; P11.2@67.722,35.56 v1(67.722,34.296) 69.514,34.296 70.028,33.782 70.028,23.868 69.901,23.741 69.901,23.707 59.097,12.903 40.437,12.903 38.532,10.998 38.125,10.998
VBAT: Bat1.1 R95.1 TP26.1 U14.A1 | length 9.7
  Top Layer w0.381: v1(14.175,16.475) 15.672,14.978 19.431,14.978 20.087,14.978 U14.A1@20.225,14.84
  Bottom Layer w0.635: Bat1.1@11.43,17.085 12.04,16.475 v1(14.175,16.475)
VBAT_EN: U14.B2 U21.4 | length 8.5
  Top Layer w0.152: v2(18.161,10.135) 18.161,9.474 U21.4@18.171,9.464 ; U14.B2@20.698,14.367 21.149,14.367 v2(21.311,14.529)
  Mid-Layer 1 w0.152: v2(18.161,10.135) 18.999,10.973 18.999,14.351 19.406,14.757 21.082,14.757 v2(21.311,14.529)
VBOOST_SRC: C80.2 L80.1 SW8.6 TP28.1 U12.1 U12.3 | length 48.1
  Top Layer w0.15: 11.961,27.736 11.961,27.101 12.309,26.753 U12.3@12.309,26.466
  Top Layer w0.25: v1(13.6,22.675) v1@13.604,22.679 ; TP28.1@14.754,22.679 TP28.1@14.757,22.682
  Top Layer w0.35: 9.004,26.47 C80.2@9.004,26.871 ; C80.2@9.004,26.875 9.2,27.071 9.2,27.175 9.761,27.736 11.961,27.736 13.358,27.736 13.739,27.355 13.739,26.814 U12.1@13.4,26.475
  Top Layer w0.5: v1@13.604,22.679 TP28.1@14.754,22.679
  Top Layer w0.8: v1(8.195,26.879) C80.2@9,26.879 ; L80.1@9,25.5 9,26.466
  Top Layer w1.016: SW8.6@3.028,8.109 3.028,7.529 4.258,6.299 v1(6.518,6.299)
  Mid-Layer 2 w0.5: 7.071,23.471 9.129,23.471 9.925,22.675 v1(13.6,22.675)
  Mid-Layer 2 w1.016: v1(6.518,6.299) 4.751,6.299 2.575,8.475 2.575,18.975 7.071,23.471 7.071,25.755 v1(8.195,26.879)
VBOOST_SRC': D80.1 D81.1 D82.1 D83.1 SW8.5 TP32.1 | length 34.2
  Top Layer w1.016: SW8.5@5.528,8.109 v1(6.576,8.109) ; v1@21.311,29.718 22.022,29.007 25.349,29.007
  Mid-Layer 2 w1.016: v1(6.576,8.109) 7.347,8.109 9.779,10.541 9.779,16.229 13.625,20.075 14.7,20.075 16.262,21.637 16.262,22.712 19.5,25.95 19.5,28.1 v1@21.209,29.809
  other v1: 21.209,29.845
VBUS: C69.2 D80.2 FB61.2 J4.5 Q40.2 R40.1 SB48.2 U24.A2 | length 86.5
  Top Layer w0.25: U24.A2@27.683,30.153 28.054,29.782 28.054,29.771 v1@28.354,29.771 ; v1@28.441,29.741 28.941,29.741 29.212,30.012
  Top Layer w0.254: 11.258,40.329 13.233,38.354 13.259,38.354 ; Q40.2@14.168,38.735 13.665,38.735 13.284,38.354 13.259,38.354 ; R40.1@14.345,36.932 13.665,36.932 13.259,37.338 13.259,38.354
  Top Layer w0.26: v1@28.354,29.771 v1(28.4,29.725) ; v1@28.4,29.7 v1@28.441,29.741 ; 29.212,30.012 29.261,30.012
  Top Layer w0.508: v1(59.675,46.522) 59.694,46.503 59.694,46.426 60.325,45.796 J4.5@60.325,45.72
  Top Layer w0.635: v1(23.774,30.836) 23.8,30.81 D80.2@23.8,30.186
  Top Layer w1.016: 4.923,38.011 4.923,38.6 4.923,39.192 4.923,39.67 5.582,40.329 11.258,40.329 18.206,40.329 v1(18.237,40.361)
  Mid-Layer 2 w0.508: 23.978,38.252 24.206,38.481 24.206,40.894 v1(25.933,42.621) ; v1(30.328,42.621) 53.137,42.621 54.508,43.993 v1(56.921,43.993)
  Mid-Layer 2 w0.762: v1(23.774,30.836) 23.774,30.251 25.326,28.7 27.425,28.7 v1@28.4,29.675
  Mid-Layer 2 w1.016: v1(18.237,40.361) 18.771,39.827 22.403,39.827 23.978,38.252 23.978,37.084 23.114,36.22 23.114,32.614 23.774,31.953 v1(23.774,30.836)
  Bottom Layer w0.508: v1(25.933,42.621) v1(30.328,42.621) ; v1(56.921,43.993) 57.146,43.993 v1(59.675,46.522)
VBUS_IMCU: R7.2 R13.1 SB48.1 U24.A1 | length 20.6
  Top Layer w0.2: v1(33.975,25.45) 36.565,22.86 R7.2@36.6,22.86
  Top Layer w0.203: R13.1@32.225,35.71 v1(32.225,36.275)
  Top Layer w0.25: U24.A1@27.683,30.553 28.13,31 28.898,31 29.112,30.786
  Top Layer w0.26: 29.112,30.786 29.261,30.637
  Top Layer w0.381: 29.261,30.637 29.614,30.637 29.653,30.637 30.266,31.25 v1(30.325,31.25)
  Bottom Layer w0.381: v1(32.225,36.275) 32.225,35.15 30.325,33.25 v1(30.325,31.25) 33.275,28.3 33.275,26.15 v1(33.975,25.45)
VBUS_nRF: C21.1 R98.2 U1.AD2 | length 42
  Top Layer w0.25: U1.AD2@112.414,34.367 112.414,32.742 C21.1@112.539,32.617 v1@113.053,32.103
  Top Layer w0.508: R98.2@88.189,14.986 v1(88.646,14.986)
  Mid-Layer 2 w0.508: v1(106.172,13.894) 111.531,19.253 111.531,27.732 113.055,29.256 v1(113.055,32.106)
  Bottom Layer w0.508: v1(88.646,14.986) 90.678,14.986 91.77,13.894 v1(106.172,13.894)
VBUS_NRF': C68.2 C91.2 D81.2 FB60.2 R97.1 SB80.2 U10.A2 | length 95.3
  Top Layer w0.2: 85.253,11.198 85.253,11.598
  Top Layer w0.203: U10.A2@85.125,12.375 85.765,11.735 85.79,11.735
  Top Layer w0.508: 85.253,11.198 85.79,11.735 86.272,12.217 86.564,12.217 86.656,12.217 86.995,12.217
  Top Layer w0.635: D81.2@25.425,30.186 25.959,30.719 v1(25.959,31.064) ; v1(30.734,40.437) 31.801,40.437 32.24,39.998 32.24,39.573
  Top Layer w1.016: v1(58.475,21.875) 61.284,21.875 74.04,9.119 83.363,9.119 84.379,9.119 84.76,8.738 84.76,9.119 84.76,9.83 84.76,10.414 85.253,10.907 85.253,11.198
  Mid-Layer 2 w1.016: v1@26.162,31.064 26.162,34.188 27.127,35.154 27.127,36.83 v1(30.734,40.437) 32.006,41.709 48.791,41.709 v1(52.175,38.325)
  Bottom Layer w1.016: v1(52.175,38.325) 53.064,38.325 58.475,32.914 v1(58.475,21.875)
VCOM_CTS: R10.1 TP1.1 U2.AL9 U5.4 | length 46.2
  Top Layer w0.152: U2.AL9@36.839,26.827 36.839,26.139 36.7,26 R10.1@36.7,25.435 36.815,25.435 37.064,25.186 37.064,23.986 37.348,23.702 39.274,23.702 39.838,23.139 62.351,23.139 65.786,19.704 TP1.1@65.786,19.05 66.548,18.288 69.453,18.288 70.418,17.323 72.377,17.323 73.175,16.525 74.125,16.525 74.539,16.939 U5.4@74.539,18.885
VCOM_RTS: TP3.1 U2.AL5 U5.16 | length 42.8
  Top Layer w0.152: U2.AL5@36.039,26.827 36.039,26.414 35.575,25.95 35.575,24.825 36.975,23.425 39.159,23.425 39.723,22.862 61.693,22.862 62.829,21.725 v2(63.16,21.725) ; v2(64.325,21.725) 66.035,20.015 67.361,20.015 TP3.1@67.988,19.388 ; TP3.1@68.326,19.05 68.389,19.113 69.287,19.113 70.75,17.65 71.737,17.65 72.714,18.627 U5.16@72.714,19.11
  Mid-Layer 1 w0.152: v2(63.16,21.725) v2(64.325,21.725)
VCOM_RxD: TP2.1 U2.AL19 U5.11 | length 41.8
  Top Layer w0.152: U2.AL19@38.839,26.785 38.839,26.439 38.55,26.15 38.55,24.5 39.07,23.98 39.389,23.98 39.953,23.416 62.466,23.416 63.63,22.252 65.124,22.252 TP2.1@65.786,21.59 66.675,20.701 69.247,20.701 70.695,22.149 71.907,22.149 72.39,22.631 73.355,22.631 73.732,22.254 U5.11@73.732,20.532
VCOM_TxD: TP4.1 U2.U31 U5.7 | length 46.2
  Top Layer w0.152: U2.U31@41.439,29.827 41.973,29.827 42.326,29.474 42.326,26.951 41.651,26.276 41.651,24.717 41.65,24.715 41.65,24.585 41.651,24.583 41.651,24.249 42.206,23.694 62.581,23.694 63.745,22.53 67.386,22.53 TP4.1@68.326,21.59 69.705,21.59 71.434,23.319 74.826,23.319 76.251,21.895 76.251,20.566 75.592,19.907 U5.7@75.157,19.907
VDBG: P18.1 P25.1 SB59.1 SB60.1 | length 23
  Top Layer w0.203: SB60.1@75.268,43.18 75.268,41.607 75.268,41.3 75.242,41.275 75.417,41.275 77.622,41.275 78.207,40.691 84.506,40.691 85.09,40.107 P25.1@85.09,38.145 85.09,36.398 84.455,35.763 84.455,32.893 85.09,32.258 P18.1@85.09,29.89
VDD: C42.2 C45.2 C48.2 C50.2 Q40.4 R41.1 R52.1 R53.1 R54.2 R68.2 SB9.1 SB17.1 SB31.1 SB37.2 SB38.2 SB47.1 SB59.2 SW6.6 SW7.3 SW8.3 SW10.6 TP37.1 U4.A2 U5.14 U6.14 U7.14 U8.14 U9.B2 U10.B2 U18.A2 | length 65.8
  Top Layer w0.2: 8.923,62.408 v1(9.855,62.408) ; Q40.4@16.058,38.085 16.571,38.085 16.85,38.364 17.085,38.364 R41.1@17.12,38.399 18.324,38.399 18.533,38.608 v1(18.644,38.608) ; R68.2@64.516,27.325 65.055,27.325 v1(65.448,26.932) ; v1(120.929,56.286) 120.929,56.179 121.489,55.619
  Top Layer w0.254: 29.941,15.992 U18.A2@29.941,16.95 ; v1@52.75,40.75 U9.B2@53.05,41.05 ; v1(58.522,17.12) 58.59,17.052 58.59,16.798 59.202,16.185 C45.2@59.573,16.185 ; C45.2@59.588,16.185 59.588,16.888 59.592,16.891 U6.14@59.592,17.342 ; v1(71.306,20.938) 71.306,20.282 71.38,20.208 C42.2@71.38,20.193 71.38,20.178 71.388,20.17 71.403,20.17 71.665,19.907 U5.14@72.707,19.907 ; v1(73.025,41.91) 73.66,41.275 74.443,41.275 74.618,41.275 ; v1@78.892,21.717 v1@78.918,21.742 ; v1(78.892,21.742) v1@78.918,21.742 ; v1(79.273,19.304) 79.273,19.4 79.406,19.533 79.406,19.949 79.414,19.941 79.429,19.941 79.46,19.91 U7.14@80.715,19.91 ; v1(79.578,42.647) 79.597,42.665 SW7.3@80.8,42.665 ; R53.1@80.131,21.742 v1@78.918,21.742 ; R54.2@81.535,14.125 v1(81.975,14.125) ; R52.1@83.191,21.742 83.191,21.757 83.199,21.765 83.214,21.765 83.859,22.411 83.981,22.411 v1(84.049,22.479) ; v1(84.2,12.625) 84.222,12.625 84.472,12.375 U10.B2@84.73,12.375 ; U8.14@91.748,22.397 91.737,22.386 91.737,22.021 91.2,21.483 91.2,21.42 C50.2@91.192,21.412 91.192,21.397 91.2,21.389 91.215,21.389 91.401,21.203 91.421,21.203 v1(92.05,20.574) ; v1(92.202,59.512) 92.448,59.759 93.701,59.759 ; v1(106.832,53.594) 106.832,54.948 SW6.6@106.869,54.984 ; 107.292,52.225 U4.A2@107.537,52.47
  Top Layer w0.381: v1(70.815,13.945) 70.815,14.3 TP37.1@71.755,15.24 ; v1(107.823,20.498) 108.352,20.498 108.527,20.498
  Top Layer w0.508: v1(17.653,2.235) 17.674,2.214 SW10.6@18.875,2.214 ; v1@106.858,52.299 107.366,52.299
  Top Layer w0.762: v1(1.848,2.628) v1(4.185,2.628) ; SW8.3@3.027,2.559 v1(3.027,4.369) ; 29.679,15.992 29.693,15.979 v1(29.693,14.986)
  Bottom Layer w1.016: v1(107.823,20.498) 109.55,20.498 v1(112.268,17.78)
  Bottom Layer w1.27: v1@70.587,45.009 v1(78.511,45.009) ; v1(70.815,7.29) v1(70.815,13.945) ; v1(89.687,17.018) v1(99.568,17.018)
  other v1: 48.387,11.354 52.7,40.75 70.587,44.958 106.858,52.324
VDD_HV: C19.1 P20.10 P23.1 P26.10 R91.2 SB41.1 TP25.1 U1.Y2 | length 134.7
  Top Layer w0.25: v1@108.562,32.708 108.562,32.891 C19.1@109.014,33.342 109.783,34.112 110.447,34.112 111.793,35.458 111.989,35.458 112.179,35.459 112.337,35.617 U1.Y2@112.414,35.617
  Top Layer w0.762: TP25.1@10.795,48.387 10.033,48.387 9.398,49.022 9.398,51.562 10.306,52.47 P23.1@11.811,52.47 ; P23.1@11.811,52.4 13.284,52.4 14.089,51.595 16.995,51.595 v1(17,51.6) ; P20.10@41.656,44.255 v1(41.656,45.72) P20.10@41.656,47.185
  Bottom Layer w0.762: v1@16.995,51.545 17.853,50.687 41.65,50.687 ; P26.10@41.656,44.255 v1(41.656,45.72) P26.10@41.656,47.185 41.656,50.681 41.65,50.687 ; v1(108.433,32.791) 108.206,32.791 106.863,31.448 104.188,31.448 102.997,32.639 102.997,45.253 97.563,50.687 41.65,50.687
VDD_HV': P20.11 P23.2 P26.11 R91.1 SB41.2 SB81.1 U9.A1 | length 53.2
  Top Layer w0.26: U9.A1@53.45,41.45 53.45,42.05
  Top Layer w0.762: P23.2@11.811,49.86 13.284,49.86 14.089,50.665 15.781,50.665 ; 15.91,50.613 16.349,50.613 18.042,48.92 43.51,48.92 44.196,48.235 P20.11@44.196,47.185 v1(44.196,45.72) P20.11@44.196,44.255 44.196,43.18 44.822,42.554 ; 44.876,42.5 53,42.5 53.45,42.05 ; 50.35,40.987 50.35,41.012 50.35,42.424
  Bottom Layer w0.762: P26.11@44.196,44.255 v1(44.196,45.72) P26.11@44.196,47.185
VDD_IMCU: C24.1 C25.1 C26.1 C27.1 C28.1 C31.1 C32.1 C33.1 C34.1 C35.2 J4.1 R8.2 SB37.1 TP35.1 TP48.1 U2.A19 U2.AC1 U2.AG1 U2.AJ31 U2.AL3 U2.AL7 U2.AL11 U2.AL17 U2.AL25 U2.B8 U2.B28 U2.C1 U2.E1 U2.E31 U2.L1 U2.N31 U2.U1 U18.A1 | length 71.8
  Top Layer w0.15: C26.1@33.964,27.812 33.987,27.835 35.031,27.835 U2.AG1@35.039,27.827 ; C26.1@34.021,27.869 33.975,27.916 33.975,28.15 v1(34.3,28.475) 34.452,28.627 U2.AC1@35.039,28.627 ; v1(34.15,30.25) 33.949,30.049 C25.1@33.949,29.677 34.152,29.677 34.302,29.827 U2.U1@35.039,29.827 ; v1(34.9,25.9) 35.639,26.639 U2.AL3@35.639,26.827 ; v1(36.125,25.85) 36.525,26.25 36.525,26.741 U2.AL7@36.439,26.827 ; U2.AL11@37.239,26.827 37.239,26.127 37.415,25.95 ; C27.1@37.415,25.387 37.479,25.45 v1(38.025,25.45) ; C27.1@37.415,25.437 37.415,25.95 ; U2.AL17@38.439,26.827 38.439,26.527 37.862,25.95 37.415,25.95 ; v1@39.025,25.45 v1(39.038,25.45) 39.038,25.437 C31.1@39.564,25.437 39.564,26.039 40.039,26.514 U2.AL25@40.039,26.827 ; U2.B28@40.639,32.827 40.639,32.902 40.776,33.039 40.776,33.484 41.232,33.939 42,33.939 42.426,34.365 C34.1@43.05,34.365 ; U2.AJ31@41.439,27.427 41.698,27.427 v1(41.875,27.25) ; U2.N31@41.439,30.627 42.064,30.627 42.336,30.354 C32.1@42.715,30.354 ; C32.1@42.715,30.352 42.715,29.785 v1(42.775,29.725) ; C34.1@43.05,34.35 v1(43.625,34.35)
  Top Layer w0.152: U2.E31@41.439,32.227 41.989,32.227 42.253,32.491 C33.1@42.715,32.491 42.804,32.491 v1(42.804,32.956)
  Top Layer w0.187: C35.2@35.714,35.352 35.714,35.186 36.12,34.78 36.12,34.603 36.682,34.042 36.682,32.87 U2.B8@36.639,32.827
  Top Layer w0.2: v1(33.55,31.4) 33.598,31.352 34.636,31.352 34.961,31.027 U2.L1@35.039,31.027 ; C24.1@33.939,32.437 34.549,32.437 ; U2.E1@35.039,32.227 35.034,32.232 34.809,32.232 34.601,32.439 34.789,32.627 U2.C1@35.039,32.627
  Top Layer w0.225: U2.A19@38.839,33.227 38.839,34.439 39.101,34.701 39.101,34.914 39.239,35.052 39.264,35.052 39.3,35.088 v1(39.3,35.725)
  Top Layer w0.25: C24.1@33.939,32.437 v1(33.939,33.065)
  Top Layer w0.254: 30.347,16.196 30.347,16.407 U18.A1@30.347,16.958 ; v2(57.364,37.444) 57.364,38.632 57.372,38.64 R8.2@57.375,38.64
  Top Layer w0.3: v1@35.039,35.327 v1(35.064,35.327) 35.689,35.327 C35.2@35.714,35.352
  Top Layer w0.381: v1(60.325,40.64) 60.403,40.562 60.784,40.562 TP35.1@61.722,39.624
  Top Layer w0.762: 30.678,15.992 v1(31.16,15.992)
  Mid-Layer 1 w0.254: v1(43.625,34.35) 46.719,37.444 v2(57.364,37.444) 61.069,37.444 v1(61.075,37.45)
  Mid-Layer 2 w0.762: v1(31.16,15.992) 34.242,15.992 37.025,18.775 37.025,26.325
  Bottom Layer w0.203: v1(60.325,40.64) 61.087,39.878 TP48.1@61.087,39.268 ; v1(61.075,37.45) 61.087,37.462 TP48.1@61.087,38.656
VDD_NRF: C6.1 C7.1 C8.1 C12.1 C14.1 L4.1 P20.1 P22.1 P26.1 R90.2 SB18.1 SB40.1 SW9.6 TP24.1 U1.A22 U1.AD14 U1.AD23 U1.B1 U1.W1 | length 194.8
  Top Layer w0.25: v1(106.714,33.342) C6.1@107.613,33.342 107.664,33.342 108.916,34.595 110.371,34.595 111.641,35.865 U1.W1@111.914,35.865 ; v1(109.639,42.217) 110.039,41.817 C14.1@110.039,41.444 110.837,41.444 U1.B1@111.914,40.367 ; v1@110.189,31.117 L4.1@110.189,31.992 ; C7.1@115.414,32.992 U1.AD14@115.414,34.367 ; C7.1@115.49,32.992 116.205,32.277 v1@116.205,32.004 ; v1(116.915,43.067) 116.915,42.641 C12.1@117.389,42.167 117.414,42.142 U1.A22@117.414,40.867 ; U1.AD23@117.914,34.367 118.189,34.092 C8.1@118.189,32.992 118.313,32.868 v1(119.71,32.868)
  Top Layer w0.381: v1(107.975,19.507) 108.255,19.228 108.352,19.228 108.527,19.228
  Top Layer w0.762: TP24.1@10.795,45.847 10.795,45.286 11.811,44.27 13.284,44.27 14.064,43.49 16.058,43.49 18.288,45.72 v1(18.796,45.72) ; P20.1@18.796,44.255 v1(18.796,45.72) ; P20.1@18.796,47.185 v1(18.796,45.72) ; v1(19.914,41.377) 20.955,41.377 21.749,40.583 SW9.6@21.749,39.906
  Mid-Layer 2 w0.508: v1(106.714,33.342) 108.433,31.623 108.433,30.048 110.744,27.737 110.744,21.895 108.356,19.507 v1(107.975,19.507)
  Mid-Layer 2 w0.762: v1(18.796,45.72) 18.8,45.724 18.8,51.525 v1(18.95,51.675)
  Bottom Layer w0.4: v1(106.714,33.342) 106.894,33.522 108.946,33.522 110.189,32.28 v1@110.189,31.318 ; v1(109.639,42.217) 110.489,43.067 v1@116.839,43.067 ; v1(110.189,31.244) 113.427,31.244 114.054,31.871 118.054,31.871 119.05,32.868 v1(119.71,32.868)
  Bottom Layer w0.762: P26.1@18.796,47.185 v1(18.796,45.72) P26.1@18.796,44.255 18.796,42.494 v1(19.914,41.377) ; v1(18.95,51.675) 98.109,51.675 100.407,49.377 106.477,49.377 107.729,48.126 107.729,42.493 ; v1(106.714,33.342) 106.692,33.364 106.692,41.456 107.729,42.493 ; v1(109.639,42.217) 107.729,42.217 107.729,42.493
  other v1: 116.205,31.801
